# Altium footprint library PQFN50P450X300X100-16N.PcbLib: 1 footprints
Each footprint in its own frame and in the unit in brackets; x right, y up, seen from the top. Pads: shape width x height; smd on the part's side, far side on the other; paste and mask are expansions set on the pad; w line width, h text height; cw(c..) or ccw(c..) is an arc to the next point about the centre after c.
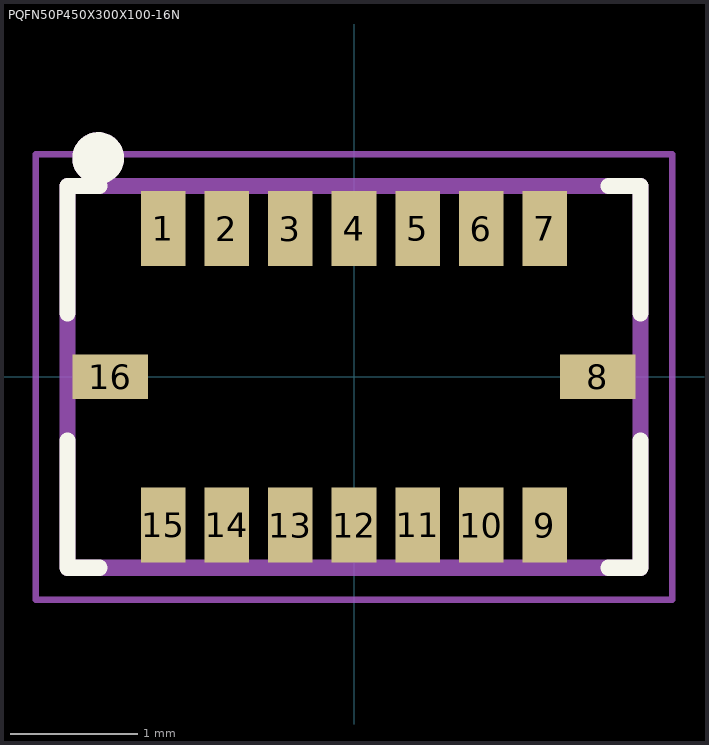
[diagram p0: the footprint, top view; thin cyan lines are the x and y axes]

## PQFN50P450X300X100-16N [mm]
pads (16):
  rect 0.35x0.59 smd: 1(-1.5,1.165) 2(-1,1.165) 3(-0.5,1.165) 4(0,1.165) 5(0.5,1.165) 6(1,1.165) 7(1.5,1.165) 9(1.5,-1.165) 10(1,-1.165) 11(0.5,-1.165) 12(0,-1.165) 13(-0.5,-1.165) 14(-1,-1.165) 15(-1.5,-1.165)
  rect 0.59x0.35 smd: 8(1.915,0) 16(-1.915,0)
Top Overlay:
  circle w0.254: c-2.01,1.719 r0.076
  lines w0.127: -2.25,-0.5 -2.25,-1.5 -2,-1.5 ; -2.25,0.5 -2.25,1.5 -2,1.5 ; 2,-1.5 2.25,-1.5 2.25,-0.5 ; 2,1.5 2.25,1.5 2.25,0.5
Mechanical 13:
  circle w0.254: c-2.01,1.719 r0.076
  lines w0.127: -2.25,-1.5 2.25,-1.5 2.25,1.5 -2.25,1.5 -2.25,-1.5
Mechanical 15:
  lines w0.05: -2.5,-1.75 2.5,-1.75 2.5,1.75 -2.5,1.75 -2.5,-1.75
